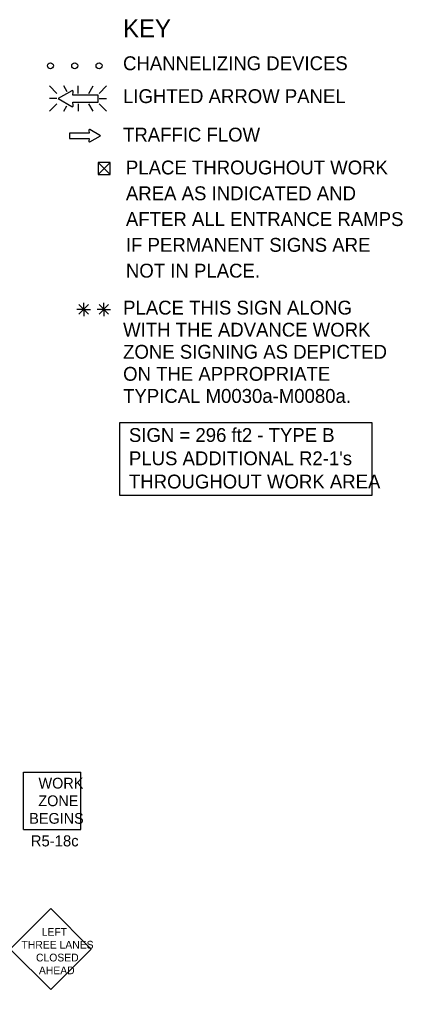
# Model space of a CAD drawing. Extents: x 16724 to 18475, y 7025 to 8210.
# Drawn here: x 17161 to 17418, y 7541 to 8192 of the extents above; entities that cross this region are included whole.
import ezdxf

# ---------------------------------------------------------------- set-up
doc = ezdxf.new("R2010")
doc.units = 0
for name, color, linetype in [('MT_SCRATCH_LEVEL_E', 7, 'Continuous'), ('TRAFFIC_SIGNS_PR', 7, 'Continuous'), ('TYPICAL_TEXT_DIMEN_EX', 7, 'Continuous'), ('TYPICAL_TEXT_DIMEN_PR', 7, 'Continuous')]:
    doc.layers.add(name, color=color, linetype=linetype)

msp = doc.modelspace()

# ---------------------------------------------------------------- linework, layer by layer
at = {"layer": 'MT_SCRATCH_LEVEL_E'}
for p, q in [((17215.87, 8113.66), (17208.63, 8117.77)), ((17208.26, 8115.51), (17195.01, 8115.51)), ((17195.01, 8115.51), (17195.01, 8111.77)), ((17195.01, 8111.77), (17208.26, 8111.77)), ((17207.95, 8117.29), (17208.26, 8115.51)), ((17208.26, 8111.77), (17207.95, 8109.99)), ((17208.63, 8109.51), (17215.87, 8113.66))]:
    msp.add_line(p, q, dxfattribs=at)
for centre, start, end in [((17208.41, 8117.36), 60.42484, 189.96381), ((17208.41, 8109.92), 170.03619, 299.77312)]:
    msp.add_arc(centre, 0.463, start, end, dxfattribs=at)
at = {"layer": 'TRAFFIC_SIGNS_PR'}
for p, q in [((17181.68, 8147.04), (17186.62, 8142.11)), ((17193.45, 8143.22), (17191.24, 8147.04)), ((17200.77, 8142.11), (17200.77, 8147.04)), ((17208, 8142.11), (17210.85, 8147.04)), ((17214.92, 8142.11), (17219.85, 8147.05)), ((17186.62, 8138.55), (17181.68, 8138.55)), ((17214.92, 8138.55), (17219.85, 8138.55)), ((17181.68, 8130.07), (17186.62, 8135)), ((17191.19, 8130.06), (17193.31, 8133.72)), ((17200.77, 8135), (17200.77, 8130.06)), ((17210.9, 8130.06), (17208.05, 8135)), ((17214.92, 8135), (17219.85, 8130.06)), ((17164.28, 7648.67), (17164.28, 7687.07)), ((17164.28, 7687.07), (17202.68, 7687.07)), ((17202.68, 7648.67), (17202.68, 7687.07)), ((17164.28, 7648.67), (17202.68, 7648.67)), ((17182.47, 7595.55), (17155.32, 7568.39)), ((17209.62, 7568.39), (17182.47, 7595.55)), ((17155.32, 7568.39), (17182.47, 7541.24)), ((17182.47, 7541.24), (17209.62, 7568.39))]:
    msp.add_line(p, q, dxfattribs=at)
for points in [[(17196.69, 8143.83), (17187.4, 8138.55), (17196.7, 8133.23)], [(17197.57, 8133.86), (17197.17, 8136.13), (17214.18, 8136.13), (17214.18, 8140.93), (17197.17, 8140.93), (17197.57, 8143.21)]]:
    msp.add_lwpolyline(points, dxfattribs=at)
for centre in [(17182.25, 8160.58), (17198.55, 8160.58), (17214.85, 8160.58)]:
    msp.add_circle(centre, 2, dxfattribs=at)
for centre, radius, start, end in [((17196.98, 8143.31), 0.598, 350.73078, 118.89165), ((17196.98, 8133.76), 0.597, 241.48329, 9.95933)]:
    msp.add_arc(centre, radius, start, end, dxfattribs=at)
at = {"layer": 'TYPICAL_TEXT_DIMEN_EX'}
msp.add_lwpolyline([(17228.68, 7921.37), (17397.68, 7921.37), (17397.68, 7872.54), (17228.68, 7872.54)], close=True, dxfattribs=at)
at = {"layer": 'TYPICAL_TEXT_DIMEN_PR'}
for p, q in [((17214.35, 8095.65), (17222.35, 8087.65)), ((17214.35, 8087.65), (17222.35, 8095.65)), ((17201.37, 8000.48), (17207.74, 7994.11)), ((17207.74, 8000.48), (17201.37, 7994.11)), ((17204.55, 7997.3), (17204.55, 8001.75)), ((17214.87, 8000.48), (17221.25, 7994.11)), ((17221.25, 8000.48), (17214.87, 7994.11)), ((17218.06, 7997.3), (17218.06, 8001.75)), ((17204.55, 7997.3), (17200.02, 7997.3)), ((17204.55, 7997.3), (17207.74, 7997.3)), ((17204.55, 7997.3), (17209.03, 7997.3)), ((17204.55, 7997.3), (17204.55, 7992.8)), ((17218.06, 7997.3), (17213.53, 7997.3)), ((17218.06, 7997.3), (17221.25, 7997.3)), ((17218.06, 7997.3), (17222.54, 7997.3)), ((17218.06, 7997.3), (17218.06, 7992.8))]:
    msp.add_line(p, q, dxfattribs=at)
msp.add_lwpolyline([(17214.35, 8095.65), (17214.35, 8087.65), (17222.35, 8087.65), (17222.35, 8095.65)], close=True, dxfattribs=at)
msp.add_open_spline([(17315.92, 8086.33), (17315.94, 8086.33), (17315.95, 8086.33), (17315.95, 8086.33)], degree=2, dxfattribs=at)

# ---------------------------------------------------------------- texts
at = {"layer": 'TRAFFIC_SIGNS_PR'}
for s, height, p in [('WORK', 7.217, (17174.28, 7676.03)), ('ZONE', 7.217, (17174.16, 7664.22)), ('BEGINS', 7.217, (17168.09, 7652.42)), ('R5-18c', 7.44, (17169.09, 7637.23)), ('LEFT', 5.2, (17176.41, 7577.32)), ('THREE LANES', 5.2, (17162.86, 7568.72)), ('CLOSED', 5.2, (17172.59, 7560.12)), ('AHEAD', 5.2, (17174.54, 7551.52))]:
    msp.add_text(s, height=height, dxfattribs=at).set_placement(p)
at = {"layer": 'TYPICAL_TEXT_DIMEN_EX'}
for s, height, p in [('KEY', 12, (17230.94, 8179.68)), ('CHANNELIZING DEVICES', 9.3, (17230.94, 8157.63)), ('LIGHTED ARROW PANEL', 9.3, (17230.94, 8135.58)), ('TRAFFIC FLOW', 9.3, (17230.94, 8109.78)), ('PLACE THROUGHOUT WORK', 9.31, (17232.86, 8087.74)), ('AREA AS INDICATED AND', 9.31, (17232.86, 8070.45)), ('AFTER ALL ENTRANCE RAMPS', 9.31, (17232.86, 8053.16)), ('IF PERMANENT SIGNS ARE', 9.31, (17232.86, 8035.87)), ('NOT IN PLACE.', 9.31, (17232.86, 8018.58)), ('PLACE THIS SIGN ALONG', 9.3, (17231, 7993.8)), ('WITH THE ADVANCE WORK', 9.3, (17231, 7979)), ('ZONE SIGNING AS DEPICTED', 9.3, (17231, 7964.2)), ('ON THE APPROPRIATE', 9.3, (17231, 7949.4)), ('TYPICAL M0030a-M0080a.', 9.3, (17231, 7934.6)), ('SIGN = 296 ft2 - TYPE B', 9.3, (17234.9, 7908.39)), ("PLUS ADDITIONAL R2-1's", 9.3, (17234.9, 7892.79)), ('THROUGHOUT WORK AREA', 9.3, (17234.9, 7877.19))]:
    msp.add_text(s, height=height, dxfattribs=at).set_placement(p)

doc.saveas('drawing.dxf')
